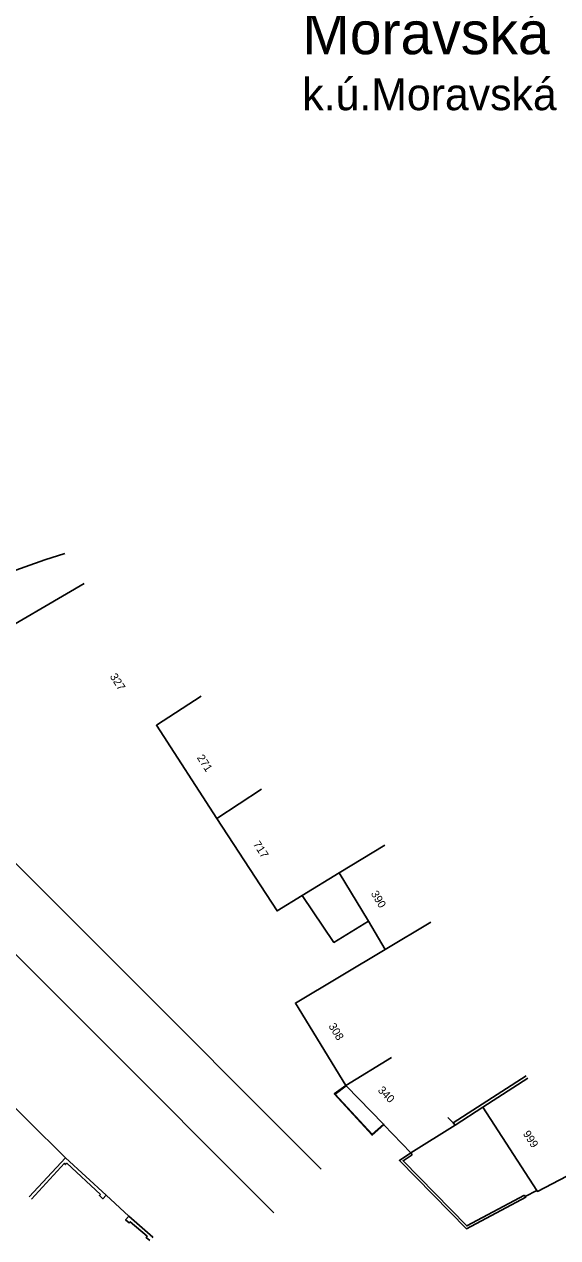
# Model space of a CAD drawing. Extents: x -577457 to -568404, y -1208466 to -1201387.
# Drawn here: x -573600.3 to -573550.3, y -1206438 to -1206324.2 of the extents above; entities that cross this region are included whole.
import ezdxf

# ---------------------------------------------------------------- set-up
doc = ezdxf.new("R2010")
doc.units = 0
for name, color, linetype in [('BUDOVY_MĚŘ', 7, 'Continuous'), ('NÁZEV_K_Ú', 7, 'Continuous'), ('NÁZVY_SÍDEL_JEDNOTKY', 7, 'Continuous'), ('ROZHRANÍ_PLOCH', 7, 'Continuous'), ('ZN_DOPLŇKOVÉ', 7, 'Continuous'), ('Č_POPIS_ORIENT', 7, 'Continuous')]:
    doc.layers.add(name, color=color, linetype=linetype)

msp = doc.modelspace()

# ---------------------------------------------------------------- linework, layer by layer
at = {"layer": 'BUDOVY_MĚŘ'}
for points in [[(-573583.73, -1206387.19), (-573587.93, -1206389.91), (-573582.28, -1206398.64)], [(-573582.28, -1206398.64), (-573578.09, -1206395.9)], [(-573574.27, -1206405.87), (-573576.62, -1206407.31), (-573582.28, -1206398.64)], [(-573566.52, -1206401.14), (-573570.79, -1206403.74)], [(-573570.79, -1206403.74), (-573574.27, -1206405.87)], [(-573568.06, -1206408.27), (-573570.79, -1206403.74)], [(-573566.5, -1206410.93), (-573568.06, -1206408.27)], [(-573562.21, -1206408.36), (-573566.5, -1206410.93)], [(-573566.5, -1206410.93), (-573574.91, -1206415.96), (-573570.17, -1206423.68)], [(-573570.17, -1206423.68), (-573565.91, -1206421.07)], [(-573553.13, -1206423.01), (-573557.33, -1206425.73)], [(-573570.13, -1206423.73), (-573570.17, -1206423.68)], [(-573566.64, -1206427.32), (-573570.13, -1206423.73)], [(-573557.33, -1206425.73), (-573552.28, -1206433.52)], [(-573560.62, -1206426.67), (-573560.13, -1206427.17)], [(-573566.6, -1206427.36), (-573566.64, -1206427.32)], [(-573564.08, -1206429.99), (-573566.6, -1206427.36)], [(-573559.92, -1206427.39), (-573564.08, -1206429.99)], [(-573560.13, -1206427.17), (-573559.92, -1206427.39)], [(-573552.28, -1206433.52), (-573552.22, -1206433.61), (-573546.72, -1206430.75)]]:
    msp.add_lwpolyline(points, dxfattribs=at)
at = {"layer": 'ROZHRANÍ_PLOCH'}
for points in [[(-573596.52, -1206373.81), (-573598.39, -1206374.41), (-573600.24, -1206375.05), (-573602.09, -1206375.73)], [(-573594.71, -1206376.61), (-573604.13, -1206382.12), (-573604.96, -1206382.63), (-573605.77, -1206383.18), (-573606.56, -1206383.75), (-573607.32, -1206384.36), (-573608.06, -1206385), (-573608.77, -1206385.67), (-573609.45, -1206386.37), (-573610.1, -1206387.1), (-573610.72, -1206387.85), (-573611.32, -1206388.63), (-573611.87, -1206389.43), (-573612.4, -1206390.25), (-573612.89, -1206391.09), (-573572.48, -1206431.52)], [(-573628.29, -1206384.19), (-573576.92, -1206435.61)], [(-573560.13, -1206427.17), (-573553.28, -1206422.78)], [(-573566.6, -1206427.36), (-573567.72, -1206428.34), (-573571.26, -1206424.48), (-573570.17, -1206423.68)], [(-573566.64, -1206427.32), (-573567.71, -1206428.25), (-573571.17, -1206424.49), (-573570.13, -1206423.73)], [(-573559.92, -1206427.39), (-573557.33, -1206425.73)], [(-573596.46, -1206430.45), (-573599.85, -1206434.12)], [(-573592.65, -1206433.97), (-573596.46, -1206430.45)], [(-573553.36, -1206434.08), (-573553.31, -1206434.16), (-573558.88, -1206437.12), (-573565.16, -1206430.7), (-573564.08, -1206429.99)], [(-573564.08, -1206429.99), (-573563.96, -1206430.18)], [(-573593.18, -1206433.89), (-573593.28, -1206434), (-573592.95, -1206434.3), (-573592.65, -1206433.97)], [(-573553.36, -1206434.08), (-573552.28, -1206433.52)], [(-573592.65, -1206433.97), (-573590.53, -1206435.93)], [(-573553.42, -1206433.96), (-573553.36, -1206434.08)], [(-573590.53, -1206435.93), (-573590.82, -1206436.27), (-573590.48, -1206436.56), (-573590.39, -1206436.45), (-573588.8, -1206437.82), (-573588.9, -1206437.93), (-573588.56, -1206438.23)], [(-573588.33, -1206437.96), (-573588.27, -1206437.89), (-573590.53, -1206435.93)]]:
    msp.add_lwpolyline(points, dxfattribs=at)
at = {"layer": 'ZN_DOPLŇKOVÉ'}
for points in [[(-573574.27, -1206405.87), (-573571.29, -1206410.27), (-573568.06, -1206408.27)], [(-573596.46, -1206430.45), (-573603.55, -1206423.47), (-573605.83, -1206421.17), (-573608.77, -1206418.15), (-573613.27, -1206413.48), (-573617.65, -1206409.05)], [(-573563.96, -1206430.18), (-573564.81, -1206430.74), (-573558.84, -1206436.84), (-573553.42, -1206433.96)], [(-573593.18, -1206433.89), (-573596.33, -1206430.98), (-573596.44, -1206431.09), (-573596.55, -1206430.98), (-573599.63, -1206434.33)]]:
    msp.add_lwpolyline(points, dxfattribs=at)

# ---------------------------------------------------------------- texts
at = {"layer": 'NÁZEV_K_Ú'}
msp.add_text('k.ú.Moravská Nová Ves', height=3, dxfattribs=at).set_placement((-573574.26, -1206332.25))
at = {"layer": 'NÁZVY_SÍDEL_JEDNOTKY'}
msp.add_text('Moravská Nová Ves', height=4, dxfattribs=at).set_placement((-573574.26, -1206327))
at = {"layer": 'Č_POPIS_ORIENT'}
for s, rotation, p in [('327', 302.91, (-573592.33, -1206385.34)), ('271', 302.89, (-573584.17, -1206392.95)), ('717', 303.15, (-573578.91, -1206401.06)), ('390', 301.08, (-573567.86, -1206405.69)), ('308', 301.52, (-573571.83, -1206418.11)), ('340', 314.15, (-573567.23, -1206424.18)), ('666', 122.96, (-573552.07, -1206429.2))]:
    msp.add_text(s, height=0.75, rotation=rotation, dxfattribs=at).set_placement(p)

doc.saveas('drawing.dxf')
